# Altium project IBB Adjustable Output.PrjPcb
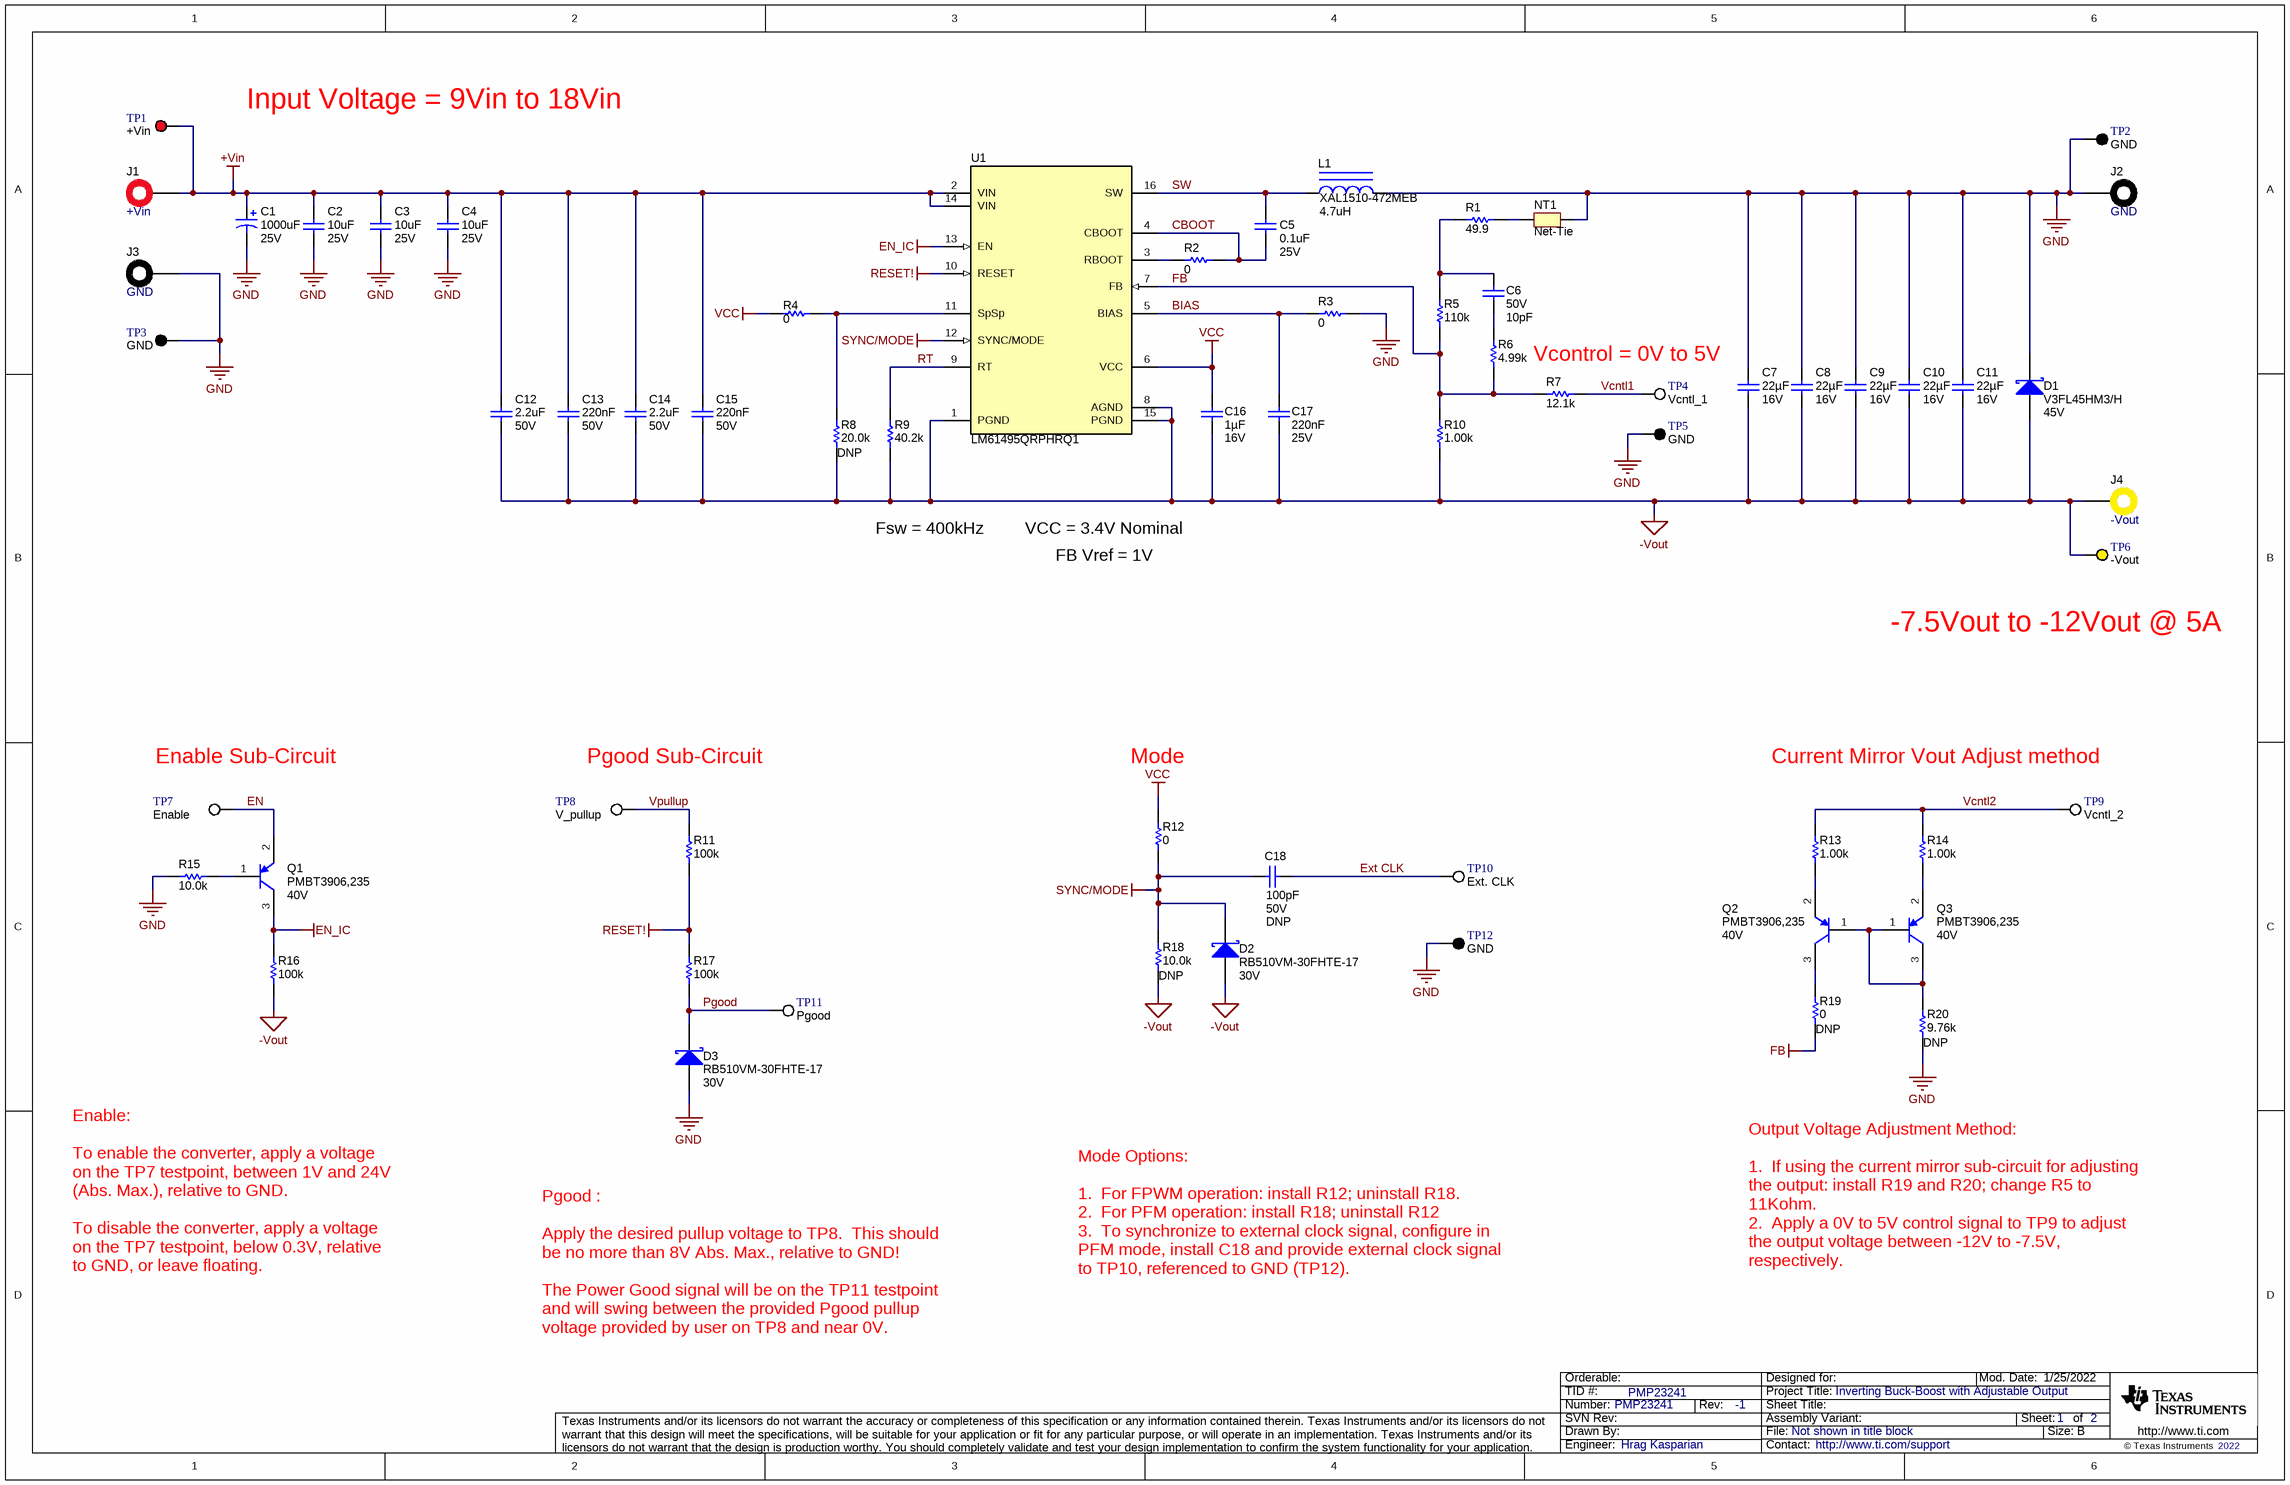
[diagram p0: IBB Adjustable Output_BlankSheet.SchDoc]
CopyrightYear: 2022; PCB_Layout: Hrag Kasparian; PCB_Rev: A; PRJ_Engineer: Hrag Kasparian; PRJ_Number: PMP23241; PRJ_Title: Inverting Buck-Boost with Adjustable Output; SCH_Rev: -1; TechSupport: http://www.ti.com/support; TID: PMP23241
2 sheets, 76 parts. Net scope: global (net labels, ports and power ports of the same name join across sheets).
Board file: IBB Adjustable Output.PcbDoc
Sheets:
  IBB Adjustable Output_BlankSheet.SchDoc
  IBB Adjustable Output_Hardware.SchDoc

## Sheet IBB Adjustable Output_BlankSheet.SchDoc
size 431 x 279 mm; Date: Not shown in title block; ApprovedBy: Not shown in title block; CheckedBy: Not shown in title block; Author: Not shown in title block; CompanyName: Not shown in title block; Engineer: Not shown in title block; Organization: Not shown in title block; Address1: Not shown in title block; Address2: Not shown in title block; Address3: Not shown in title block; Address4: Not shown in title block; DocumentNumber: 1; Revision: Use project parameter SCH_Rev; SheetNumber: 1; SheetTotal: 2; PageSetup: Record=PageOptions¦CenterHorizontal=True¦CenterVertical=True¦PrintScale=1.00¦XCorrection=1.00¦YCorrection=1.00¦PrintKind=0¦BorderSize=5000000¦LeftOffset=0¦BottomOffset=0¦Orientation=2¦PaperLength=1000¦PaperWidth=1000¦Scale=100¦PaperSource=15¦PrintQuality=600¦MediaType=1¦DitherType=10¦PaperKind=Letter¦PrintScaleMode=1

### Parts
C1  value 1000uF  Value1: 25V  [CAPSMT_62_LH0]  (hidden comment: EMXB250ARA102MLH0S)
C2  value 10uF  Value1: 25V  [1210_270L]  (hidden comment: GCM32ER71E106KA57K)
C3  value 10uF  Value1: 25V  [1210_270L]  (hidden comment: GCM32ER71E106KA57K)
C4  value 10uF  Value1: 25V  [1210_270L]  (hidden comment: GCM32ER71E106KA57K)
C5  value 0.1uF  Value1: 25V  [0603L]  (hidden comment: CGA3E2X7R1E104K080AA)
C6  VDC_V: 50V  ValueDisplayed: 10pF  [0402L]
C7  VDC_V: 16V  ValueDisplayed: 22µF  [1210_270L]  (hidden comment: CL32B226KOJVPNE)
C8  VDC_V: 16V  ValueDisplayed: 22µF  [1210_270L]  (hidden comment: CL32B226KOJVPNE)
C9  VDC_V: 16V  ValueDisplayed: 22µF  [1210_270L]  (hidden comment: CL32B226KOJVPNE)
C10  VDC_V: 16V  ValueDisplayed: 22µF  [1210_270L]  (hidden comment: CL32B226KOJVPNE)
C11  VDC_V: 16V  ValueDisplayed: 22µF  [1210_270L]  (hidden comment: CL32B226KOJVPNE)
C12  value 2.2uF  Value1: 50V  [C1206]  (hidden comment: CL31B225KBHVPNE)
C13  Cap_F: 220nF  VDC_V: 50V  [0603L]  (hidden comment: CGA3E3X7R1H224K080AB)
C14  value 2.2uF  Value1: 50V  [C1206]  (hidden comment: CL31B225KBHVPNE)
C15  Cap_F: 220nF  VDC_V: 50V  [0603L]  (hidden comment: CGA3E3X7R1H224K080AB)
C16  Cap_F: 1µF  VDC_V: 16V  [0603L]  (hidden comment: CGA3E1X7R1C105K080AC)
C17  Cap_F: 220nF  VDC_V: 25V  [0603L]  (hidden comment: GCM188R71E224KA55D)
C18  DNP  VDC_V: 50V  ValueDisplayed: 100pF  [0402L]
D1  V3FL45HM3/H  value 45V  [DO-219AB]
D2  RB510VM-30FHTE-17  value 30V  [SOD-323]
D3  RB510VM-30FHTE-17  value 30V  [SOD-323]
J1  +Vin  [6091]
J2  GND  [6092]
J3  GND  [6092]
J4  -Vout  [CONN_108-0907-001]
L1  XAL1510-472MEB  ValueDisplayed: 4.7uH  [XAL1510]
NT1  Net-Tie  [Net-Tie_10mil]  (net tie, no BOM)
Q1  PMBT3906,235  value 40V  [SOT-23]
Q2  value 40V  PartNumber: PMBT3906,235  [SOT-23]
Q3  value 40V  PartNumber: PMBT3906,235  [SOT-23]
R1  ValueDisplayed: 49.9  [0603L]  (hidden comment: CRCW060349R9FKEA)
R2  ValueDisplayed: 0  [0603L]  (hidden comment: RMCF0603ZT0R00)
R3  ValueDisplayed: 0  [0603L]  (hidden comment: RMCF0603ZT0R00)
R4  value 0  [FP-RMCF0402ZT0R00_0402 (1005 metric)-0]  (hidden comment: RMCF0402ZT0R00)
R5  ValueDisplayed: 110k  [0402L]  (hidden comment: CRCW0402110KFKED)
R6  ValueDisplayed: 4.99k  [0402L]  (hidden comment: CRCW04024K99FKED)
R7  ValueDisplayed: 12.1k  [0402L]  (hidden comment: CRCW040212K1FKED)
R8  DNP  ValueDisplayed: 20.0k  [0402L]
R9  ValueDisplayed: 40.2k  [0402L]  (hidden comment: CRCW040240K2FKED)
R10  ValueDisplayed: 1.00k  [0402L]  (hidden comment: CRCW04021K00FKED)
R11  ValueDisplayed: 100k  [0402L]  (hidden comment: RMCF0402FT100K)
R12  value 0  [FP-RMCF0402ZT0R00_0402 (1005 metric)-0]  (hidden comment: RMCF0402ZT0R00)
R13  ValueDisplayed: 1.00k  [0402L]
R14  ValueDisplayed: 1.00k  [0402L]
R15  ValueDisplayed: 10.0k  [0402L]  (hidden comment: CRCW040210K0FKED)
R16  ValueDisplayed: 100k  [0402L]  (hidden comment: RMCF0402FT100K)
R17  ValueDisplayed: 100k  [0402L]  (hidden comment: RMCF0402FT100K)
R18  DNP  ValueDisplayed: 10.0k  [0402L]
R19  DNP  value 0  [FP-RMCF0402ZT0R00_0402 (1005 metric)-0]
R20  DNP  ValueDisplayed: 9.76k  [0402L]
TP1  +Vin  [Keystone5010]
TP2  GND  [Keystone5011]
TP3  GND  [Keystone5011]
TP4  Vcntl_1  [Keystone5012]
TP5  GND  [Keystone5011]
TP6  -Vout  [Keystone5014]
TP7  Enable  [Keystone5012]
TP8  V_pullup  [Keystone5012]
TP9  Vcntl_2  [Keystone5012]
TP10  Ext. CLK  [Keystone5012]
TP11  Pgood  [Keystone5012]
TP12  GND  [Keystone5011]
U1  LM61495QRPHRQ1  [RPH0016A]

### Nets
+Vin: C1.1(+) C2.1 C3.1 C4.1 C12.1 C13.1 C14.1 C15.1 J1.1 TP1.1 U1.2(VIN) U1.14(VIN)
-Vout: C7.2 C8.2 C9.2 C10.2 C11.2 C12.2 C13.2 C14.2 C15.2 C16.2 C17.2 D1.2(A) D2.2(A) J4.1 R8.1 R9.1 R10.1 R16.1 R18.1 TP6.1 U1.1(PGND) U1.8(AGND) U1.15(PGND)
EN_IC: Q1.3(C) R16.2 U1.13(EN)
FB: R5.1 R6.1 R7.1 R10.2 R19.1 U1.7(FB)
GND: C1.2(-) C2.2 C3.2 C4.2 C7.1 C8.1 C9.1 C10.1 C11.1 D1.1(K) D3.2(A) J2.1 J3.1 L1.2 NT1.2 R3.2 R15.1 R20.1 TP2.1 TP3.1 TP5.1 TP12.1
RESET!: R11.1 R17.2 U1.10(RESET)
SYNC/MODE: C18.2 D2.1(K) R12.1 R18.2 U1.12(SYNC/MODE)
VCC: C16.1 R4.1 R12.2 U1.6(VCC)
BIAS: C17.1 R3.1 U1.5(BIAS)
CBOOT: C5.2 R2.2 U1.4(CBOOT)
EN: Q1.2(E) TP7.1
Ext CLK: C18.1 TP10.1
Pgood: D3.1(K) R17.1 TP11.1
RT: R9.2 U1.9(RT)
SW: C5.1 L1.1 U1.16(SW)
Vcntl1: R7.2 TP4.1
Vcntl2: R13.2 R14.2 TP9.1
Vpullup: R11.2 TP8.1
NetC6_1: C6.1 R1.1 R5.2
NetC6_2: C6.2 R6.2
NetNT1_1: NT1.1 R1.2
NetQ1_1: Q1.1(B) R15.2
NetQ2_1: Q2.1(B) Q3.1(B) Q3.3(C) R20.2
NetQ2_2: Q2.2(E) R13.1
NetQ2_3: Q2.3(C) R19.2
NetQ3_2: Q3.2(E) R14.1
NetR2_1: R2.1 U1.3(RBOOT)
NetR4_2: R4.2 R8.2 U1.11(SpSp)

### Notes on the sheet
- Input Voltage = 9Vin to 18Vin
- Vcontrol = 0V to 5V
- Fsw = 400kHz
- VCC = 3.4V Nominal
- FB Vref = 1V
- (near TP6) -7.5Vout to -12Vout @ 5A
- (near TP7) Enable Sub-Circuit
- (near TP8) Pgood Sub-Circuit
- Mode
- (near TP9) Current Mirror Vout Adjust method
- Enable:
  To enable the converter, apply a voltage on the TP7 testpoint, between 1V and 24V (Abs. Max.), relative to GND.
  To disable the converter, apply a voltage on the TP7 testpoint, below 0.3V, relative to GND, or leave floating.
- Mode Options:
  1.  For FPWM operation: install R12; uninstall R18.
  2.  For PFM operation: install R18; uninstall R12
  3.  To synchronize to external clock signal, configure in PFM mode, install C18 and provide external clock signal to TP10, referenced to GND (TP12).
- Output Voltage Adjustment Method:
  1.  If using the current mirror sub-circuit for adjusting the output: install R19 and R20; change R5 to 11Kohm.
  2.  Apply a 0V to 5V control signal to TP9 to adjust the output voltage between -12V to -7.5V, respectively.
- Pgood :
  Apply the desired pullup voltage to TP8.  This should be no more than 8V Abs. Max., relative to GND!
  The Power Good signal will be on the TP11 testpoint and will swing between the provided Pgood pullup voltage provided by user on TP8 and near 0V.

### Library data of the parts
C1 = Capacitor_Polarized: CAP, Al Electrolytic, 1000uF, 25V, +/-20%, 0.1ohm ESR @ 100kHz, 1.12Arms @ 100kHz, SMT; Manufacturer: United Chemi-Con; Polarized: Y; U/M: EA
C2-C4 = Capacitor: CAP, CERM, 10uF, 25V, X7R, 10%, 1210; Manufacturer: Murata; Polarized: N; U/M: EA
C5 = Capacitor: CAP, CERM, 0.1uF, 25V, X7R, 10%, 0603; Manufacturer: TDK; Polarized: N; U/M: EA
C6 = CMP-0006307-2: CAP, CERM, 10 pF, 50 V, +/- 5%, C0G/NP0, AEC-Q200 Grade 1, 0402; Manufacturer: TDK; PartNumber: CGA2B2C0G1H100D050BA; TaMin_C: -55°C; Polarized: N; SizeAreaWB_mm2: 3; Value1: Unknown; U/M: EA; Value: 10pF; TaMax_C: 125°C; SizeZ_mm: 0.6; SizeX_mm: 1; SizeY_mm: 0.5; Cap_Case: 0402; AEC Qualified: Y; AEC Category: Q200
C7-C11 = CMP-0083755-1: CAP, CERM, 22 µF, 16 V,+/- 10%, X7R, AEC-Q200 Grade 1, 1210; Manufacturer: Samsung Electro-Mechanics; SizeAreaWB_mm2: 14.7; SizeArea_mm2: 8; AEC Qualified: Y; AEC Category: Q200; Value: 22uF; TaMax_C: 125°C; SizeZ_mm: 2.7; AEC Grade: 1; Polarized: N; TaMin_C: -55°C; SizeY_mm: 2.5; U/M: EA; SizeX_mm: 3.2; Cap_Case: 1210
C12 C14 = Capacitor: CAP, CERM, 2.2uF, 50V, X7R, 10%, 1206; Manufacturer: Samsung; Polarized: N; U/M: EA
C13 C15 = CMP-0007094-5: CAP, CERM, 0.22 uF, 50 V, +/- 10%, X7R, AEC-Q200 Grade 1, 0603; Manufacturer: TDK; TaMin_C: -55°C; ESR_ohm: 0.021699; Polarized: N; SizeAreaWB_mm2: 4.68; Value1: 0.021699 ohm; U/M: EA; Value: 0.22uF; TaMax_C: 125°C; SizeZ_mm: 1; SizeX_mm: 1.6; SizeY_mm: 0.8; Cap_Case: 0603; SizeArea_mm2: 1.28; AEC Qualified: Y; IRMS_A: 1.12496A; AEC Category: Q200
C16 = CMP-0079607-1: CAP, CERM, 1 µF, 16 V,+/- 10%, X7R, AEC-Q200 Grade 1, 0603; Manufacturer: TDK; TaMin_C: -55°C; Polarized: N; SizeAreaWB_mm2: 4.68; U/M: EA; Value: 1uF; TaMax_C: 125°C; SizeZ_mm: 1; SizeX_mm: 1.6; SizeY_mm: 0.8; Cap_Case: 0603; SizeArea_mm2: 1.28; AEC Qualified: Y; AEC Category: Q200
C17 = CMP-0007140-4: CAP, CERM, 0.22 uF, 25 V, +/- 10%, X7R, AEC-Q200 Grade 1, 0603; Manufacturer: MuRata; TaMin_C: -55°C; Polarized: N; SizeAreaWB_mm2: 4.68; Value1: Unknown; U/M: EA; Value: 0.22uF; TaMax_C: 125°C; SizeZ_mm: 1; SizeX_mm: 1.6; SizeY_mm: 0.8; Cap_Case: 0603; SizeArea_mm2: 1.28; AEC Qualified: Y; AEC Category: Q200
C18 = CMP-0006308-2: CAP, CERM, 100 pF, 50 V, +/- 5%, C0G/NP0, AEC-Q200 Grade 1, 0402; Manufacturer: TDK; PartNumber: CGA2B2C0G1H101J050BA; TaMin_C: -55°C; Polarized: N; SizeAreaWB_mm2: 3; Value1: Unknown; U/M: EA; Value: 100pF; TaMax_C: 125°C; SizeZ_mm: 0.6; SizeX_mm: 1; SizeY_mm: 0.5; Cap_Case: 0402; AEC Qualified: Y; AEC Category: Q200
D1 = Diode_Schottky: Diode, Schottky, 45V, 3A, DO-219AB (SMF); Manufacturer: Vishay; U/M: EA
D2 D3 = Diode_Schottky: Diode, Schottky, 30V, 100mA, SOD-323F; Manufacturer: Rohm; U/M: EA
J1 = CMP-0055167-2: Standard Banana Jack, Insulated, Red; Manufacturer: Keystone; CT: TRUE; Green_REACh: Passed; CNHeader: FALSE; Green_Lifecycle: Active
J2 J3 = CMP-0055168-2: Standard Banana Jack, Insulated, Black; Manufacturer: Keystone; CT: TRUE; Green_REACh: Passed; CNHeader: FALSE; Green_Lifecycle: Active
J4 = CMP-0055400-2: BANANA JACK, 15A, Insulated, Nylon,Yellow; Manufacturer: Cinch Connectivity; PartNumber: 108-0907-001; CNHeader: FALSE; Green_Lifecycle: Not Set; Green_REACh: Incomplete; CT: TRUE
L1 = CMP-0060970-1: Inductor, Shielded, Composite, 4.7 uH, 29 A, 0.00335 ohm, SMD; Manufacturer: Coilcraft; Isat: 39A @ 30% inductance drop; Irms: 29A @ 40C rise; Green_Lifecycle: Not Set; SizeAreaWB_mm2: 320.16; DCR_ohm: 3.35m; Green_REACh: Incomplete; Value: 4.7uH; Imax_A: 29A; SizeZ_mm: 10; SizeX_mm: 16.4; SizeY_mm: 15.4; SizeArea_mm2: 252.56; Ind_H: 4.7µH; AEC Category: Q200
NT1 = Net-Tie: Single point connection between nets.; SymbolCreator: codlsc
Q1-Q3 = BJT_PNP_C3B1E2: Transistor, NPN, 40V, 200mA, SOT-23-3; Manufacturer: Nexperia; CompType: Bipolar Transistor; U/M: EA
R1 = CMP-0022448-4: RES, 49.9, 1%, 0.1 W, AEC-Q200 Grade 0, 0603; Manufacturer: Vishay-Dale; Power_W: 100mW; TempCo: 100 ppm/C; Value_Code: 49R9; Value: 49.9; EIA_Code: E96; SizeX_mm: 1.6; SizeY_mm: 0.8; SizeZ_mm: 1; Value2: 0.1W; SizeArea_mm2: 1.28; AEC Qualified: Y; VDC_V: 75V; AEC Category: Q200; AEC Grade: 0
R2 R3 = CMP-0023343-3: RES, 0, 1%, 0.1 W, AEC-Q200 Grade 0, 0603; Manufacturer: Stackpole Electronics Inc; Power_W: 100mW; TempCo: ppm/C; U/M: EA; Value: 0; SizeX_mm: 1.6; SizeY_mm: 0.8; SizeZ_mm: 1; Value2: 0.1W; SizeArea_mm2: 1.28; AEC Qualified: Y; AEC Category: Q200
R4 R12 = CMP-0086542-2: RMCF/RMCP Series General Purpose Thick Film Standard Power and High Power Chip Resistor; Manufacturer: Stackpole
R5 = CMP-0025967-3: RES, 110 k, 1%, 0.063 W, AEC-Q200 Grade 0, 0402; Manufacturer: Vishay-Dale; Power_W: 63mW; TempCo: 100 ppm/C; Value: 110k; EIA_Code: E96; SizeX_mm: 1; SizeY_mm: 0.5; SizeZ_mm: 0.6; Value2: 0.063W; AEC Qualified: Y; VDC_V: 50V; AEC Category: Q200; AEC Grade: 0
R6 = CMP-0026414-2: RES, 4.99 k, 1%, 0.063 W, AEC-Q200 Grade 0, 0402; Manufacturer: Vishay-Dale; Power_W: 63mW; TempCo: 100 ppm/C; Value_Code: 4k99; Value: 4.99k; EIA_Code: E96; SizeX_mm: 1; SizeY_mm: 0.5; SizeZ_mm: 0.6; Value2: 0.063W; AEC Qualified: Y; VDC_V: 50V; AEC Category: Q200; AEC Grade: 0
R7 = CMP-0025991-3: RES, 12.1 k, 1%, 0.063 W, AEC-Q200 Grade 0, 0402; Manufacturer: Vishay-Dale; Power_W: 63mW; TempCo: 100 ppm/C; Value_Code: 12k1; Value: 12.1k; EIA_Code: E96; SizeX_mm: 1; SizeY_mm: 0.5; SizeZ_mm: 0.6; Value2: 0.063W; AEC Qualified: Y; VDC_V: 50V; AEC Category: Q200; AEC Grade: 0
R8 = CMP-0026162-2: RES, 20.0 k, 1%, 0.063 W, AEC-Q200 Grade 0, 0402; Manufacturer: Vishay-Dale; PartNumber: CRCW040220K0FKED; Power_W: 63mW; TempCo: 100 ppm/C; Value_Code: 20k0; Value: 20.0k; EIA_Code: E96; Res_ohm: 20k; SizeX_mm: 1; SizeY_mm: 0.5; SizeZ_mm: 0.6; Value2: 0.063W; AEC Qualified: Y; VDC_V: 50V; AEC Category: Q200; AEC Grade: 0
R9 = CMP-0026367-2: RES, 40.2 k, 1%, 0.063 W, AEC-Q200 Grade 0, 0402; Manufacturer: Vishay-Dale; Power_W: 63mW; TempCo: 100 ppm/C; Value_Code: 40k2; Value: 40.2k; EIA_Code: E96; SizeX_mm: 1; SizeY_mm: 0.5; SizeZ_mm: 0.6; Value2: 0.063W; AEC Qualified: Y; VDC_V: 50V; AEC Category: Q200; AEC Grade: 0
R10 = CMP-0026071-3: RES, 1.00 k, 1%, 0.063 W, AEC-Q200 Grade 0, 0402; Manufacturer: Vishay-Dale; Power_W: 63mW; TempCo: 100 ppm/C; Value_Code: 1k00; Value: 1.00k; EIA_Code: E96; Res_ohm: 1k; SizeX_mm: 1; SizeY_mm: 0.5; SizeZ_mm: 0.6; Value2: 0.063W; AEC Qualified: Y; VDC_V: 50V; AEC Category: Q200; AEC Grade: 0
R11 R16 R17 = CMP-0026753-1: RES, 100 k, 1%, 0.063 W, AEC-Q200 Grade 0, 0402; Manufacturer: Stackpole Electronics Inc; Power_W: 63mW; TempCo: 100 ppm/C; U/M: EA; Value: 100k; EIA_Code: E96; SizeX_mm: 1; SizeY_mm: 0.5; SizeZ_mm: 0.6; Value2: 0.063W; AEC Qualified: Y; VDC_V: 50V; AEC Grade: 0; AEC Category: Q200
R13 R14 = CMP-0026071-3: RES, 1.00 k, 1%, 0.063 W, AEC-Q200 Grade 0, 0402; Manufacturer: Vishay-Dale; PartNumber: CRCW04021K00FKED; Power_W: 63mW; TempCo: 100 ppm/C; Value_Code: 1k00; Value: 1.00k; EIA_Code: E96; Res_ohm: 1k; SizeX_mm: 1; SizeY_mm: 0.5; SizeZ_mm: 0.6; Value2: 0.063W; AEC Qualified: Y; VDC_V: 50V; AEC Category: Q200; AEC Grade: 0
R15 = CMP-0025958-3: RES, 10.0 k, 1%, 0.063 W, AEC-Q200 Grade 0, 0402; Manufacturer: Vishay-Dale; Power_W: 63mW; TempCo: 100 ppm/C; Value_Code: 10k0; Value: 10.0k; EIA_Code: E96; Res_ohm: 10k; SizeX_mm: 1; SizeY_mm: 0.5; SizeZ_mm: 0.6; Value2: 0.063W; AEC Qualified: Y; VDC_V: 50V; AEC Category: Q200; AEC Grade: 0
R18 = CMP-0025958-3: RES, 10.0 k, 1%, 0.063 W, AEC-Q200 Grade 0, 0402; Manufacturer: Vishay-Dale; PartNumber: CRCW040210K0FKED; Power_W: 63mW; TempCo: 100 ppm/C; Value_Code: 10k0; Value: 10.0k; EIA_Code: E96; Res_ohm: 10k; SizeX_mm: 1; SizeY_mm: 0.5; SizeZ_mm: 0.6; Value2: 0.063W; AEC Qualified: Y; VDC_V: 50V; AEC Category: Q200; AEC Grade: 0
R19 = CMP-0086542-2: RMCF/RMCP Series General Purpose Thick Film Standard Power and High Power Chip Resistor; Manufacturer: Stackpole; PartNumber: RMCF0402ZT0R00
R20 = CMP-0026622-3: RES, 9.76 k, 1%, 0.063 W, AEC-Q200 Grade 0, 0402; Manufacturer: Vishay-Dale; PartNumber: CRCW04029K76FKED; Power_W: 63mW; TempCo: 100 ppm/C; Value_Code: 9k76; Value: 9.76k; EIA_Code: E96; SizeX_mm: 1; SizeY_mm: 0.5; SizeZ_mm: 0.6; Value2: 0.063W; AEC Qualified: Y; VDC_V: 50V; AEC Category: Q200; AEC Grade: 0
TP1 = CMP-0055147-2: Test Point, Multipurpose, Red, TH; Manufacturer: Keystone Electronics; CT: TRUE; ContactFinish: Silver; Green_Lifecycle: Active; CNHeader: FALSE; Green_REACh: Passed
TP2 TP3 TP5 TP12 = CMP-0055148-2: Test Point, Multipurpose, Black, TH; Manufacturer: Keystone Electronics; CNHeader: FALSE; ContactFinish: Silver; Green_REACh: Passed; Green_Lifecycle: Active; CT: TRUE
TP4 TP7-TP11 = CMP-0055149-2: Test Point, Multipurpose, White, TH; Manufacturer: Keystone Electronics; ContactFinish: Silver; CT: TRUE; CNHeader: FALSE; Green_Lifecycle: Active; Green_REACh: Passed
TP6 = CMP-0055151-2: Test Point, Multipurpose, Yellow, TH; Manufacturer: Keystone Electronics; CNHeader: FALSE; CT: TRUE; Green_REACh: Passed; ContactFinish: Silver; Green_Lifecycle: Active
U1 = CMP-0860171-2: LM61495QRPHRQ1, RPH0016A (VQFN-HR-16); Alternate Manufacturer: Texas Instruments; SizeZ_mm: 1; AEC Category: Q200; SizeX_mm: 3.5; SizeY_mm: 4.5; AEC Qualified: Y; SizeArea_mm2: 15.75; CompType: IC; SizeAreaWB_mm2: 24.75

## Sheet IBB Adjustable Output_Hardware.SchDoc
size 431 x 279 mm; Date: Not shown in title block; ApprovedBy: Not shown in title block; CheckedBy: Not shown in title block; Author: Not shown in title block; CompanyName: Not shown in title block; Engineer: Not shown in title block; Organization: Not shown in title block; Address1: Not shown in title block; Address2: Not shown in title block; Address3: Not shown in title block; Address4: Not shown in title block; DocumentNumber: 2; Revision: Use project parameter SCH_Rev; SheetNumber: 2; SheetTotal: 2; PageSetup: Record=PageOptions¦CenterHorizontal=True¦CenterVertical=True¦PrintScale=1.00¦XCorrection=1.00¦YCorrection=1.00¦PrintKind=0¦BorderSize=5000000¦LeftOffset=0¦BottomOffset=0¦Orientation=2¦PaperLength=1000¦PaperWidth=1000¦Scale=100¦PaperSource=15¦PrintQuality=600¦MediaType=1¦DitherType=10¦PaperKind=Letter¦PrintScaleMode=1
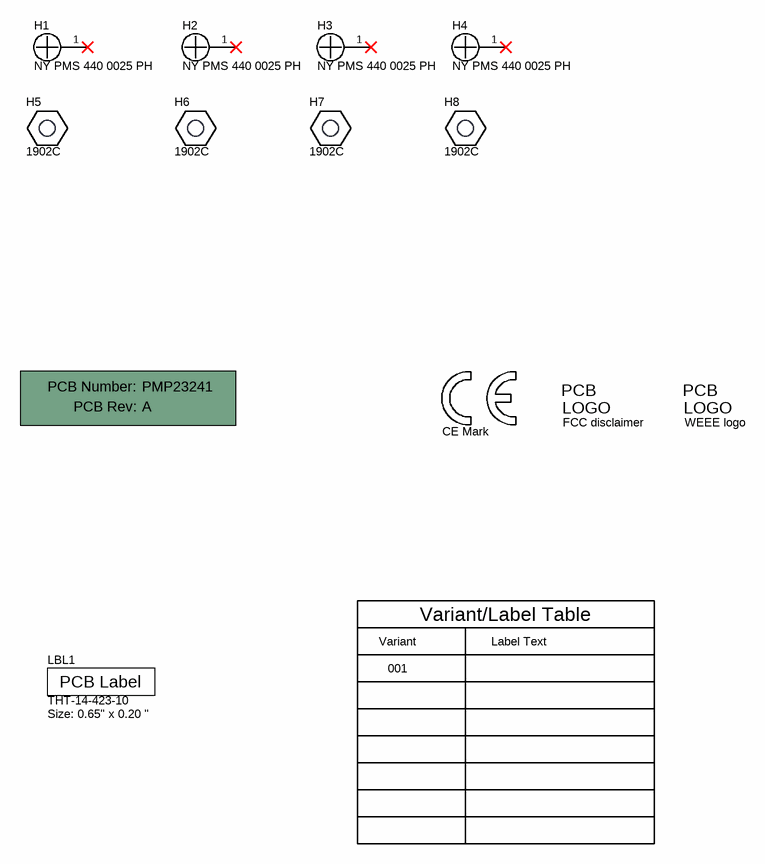
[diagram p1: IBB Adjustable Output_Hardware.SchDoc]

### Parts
!PCB1  Printed Circuit Board  (value not drawn)  (mechanical)
H1  NY PMS 440 0025 PH  [NY PMS 440 0025 PH]
H2  NY PMS 440 0025 PH  [NY PMS 440 0025 PH]
H3  NY PMS 440 0025 PH  [NY PMS 440 0025 PH]
H4  NY PMS 440 0025 PH  [NY PMS 440 0025 PH]
H5  1902C  [Keystone_1902C]
H6  1902C  [Keystone_1902C]
H7  1902C  [Keystone_1902C]
H8  1902C  [Keystone_1902C]
LBL1  THT-14-423-10  Note: Size: 0.65" x 0.20 "  [Label_650x200]
Logo1  CE Mark  [CE_Mark_5mm]  (no BOM)
Logo2  FCC disclaimer  [FCC_disclaimer]  (no BOM)
Logo3  WEEE logo  [WEEE_Minimum]  (no BOM)

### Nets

Not connected (* = marked no-connect by the designer): H1 1*; H2 1*; H3 1*; H4 1*

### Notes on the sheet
- Variant
- Variant/Label Table
- Label Text
- 001

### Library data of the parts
!PCB1 = CMP-0003618-2: Manufacturer: Any; PartNumber: PMP23241
H1-H4 = CMP-0003617-1: Machine Screw, Round, #4-40 x 1/4, Nylon, Philips panhead; Manufacturer: B&F Fastener Supply; CompType: Hardware
H5-H8 = CMP-0003610-1: Standoff, Hex, 0.5"L #4-40 Nylon; Manufacturer: Keystone; CompType: Hardware
LBL1 = CMP-0003625-1: Thermal Transfer Printable Labels, 0.650" W x 0.200" H - 10,000 per roll; Manufacturer: Brady; CompType: Label
Logo1 = CMP-0074844-1: SymbolCreator: a0412235
Logo2 = CMP-0074847-1: FCC_disclaimer; Library Reference: Logo
Logo3 = CMP-0074769-1

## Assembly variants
001: not fitted C18 R8 R18 R19 R20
